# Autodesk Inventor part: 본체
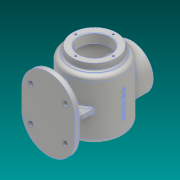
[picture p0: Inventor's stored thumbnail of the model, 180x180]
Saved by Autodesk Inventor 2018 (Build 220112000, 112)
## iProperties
Created: 2023-01
Part Number: 본체
Material: 알루미늄 6061
Document SubType Name: Modeling
Designer: 강의실01
Density: 2.7 g/cm^3
Appearance: 알루미늄 - 평지
Mass: 1034.39 g
Surface Area: 1157.53 cm^2
Volume: 383.109 cm^3
Author: 강의실01
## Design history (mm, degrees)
sketch "스케치1"
  geometry: L1 (46, -63)-(-46, -63); L2 (-46, -63)-(-46, 63); L3 (-46, 63)-(46, 63); L4 (46, 63)-(46, -63); L5 (46, -63)-(-46, 63); L6 (-46, -63)-(46, 63); 1 further point
  constraints: 12 end point, 2 midpoint, 2 parallel, 1 horizontal, 1 perpendicular
  dimensions: "d0" = 92 distance of L2.end L3.end; "d1" = 126 distance of L1.end L2.end
extrude "돌출1" new body sketch "스케치1" distance "d2" = 10; taper "d3" = 0 deg
sketch "스케치2"
  geometry: L1 (0, 63)-(0, -63) reference; L2 (107, 63)-(107, 46); L3 (107, 46)-(125, 46); L4 (118, 51)-(130, 51); L5 (130, 51)-(130, -48.087); L6 (125, 46)-(125, -44.83); L7 (118, 63)-(118, 51); L8 (80, 59)-(80, -59); L9 (107, 63)-(118, 63); A1 r 120 centre (80, 61) between (80, -59) and (130, -48.087); A2 r 115 centre (80, 61) between (80, -54) and (125, -44.83); 3 further points
  constraints: 16 end point, 4 point on circle, 3 perpendicular, 3 vertical, 2 centre point, 2 midpoint, 1 horizontal, 1 horizontal alignment, 1 point on line
  dimensions: "d20" = 5 distance between parallel lines of L6 L5; "d21" = 54 diameter of L2 L8; "d22" = 76 diameter of L7 L8; "d23" = 90 diameter of L6 L8; "d26" = 100 diameter of L5 L8 (derived); "d120" = 59 vertical distance of L8.end point (0, 0); "d122" = 160 diameter of L1 L8; "d124" = 17 distance between parallel lines of L3 L9; "d125" = 5 distance between parallel lines of L3 L4; "d126" = 120 radius of A1; "d127" = 5 radial gap between concentric circles of A1 A2; "d128" = 122 distance from line of L8.end L9 (derived); "d129" = 80 distance from line of A1.centre L1; "d133" = 51 distance from line of point (80, 0) L4
revolve "회전1" sketch "스케치2" stored, may be unused: angle "d39" = 90 deg
node "작업 평면1"
sketch "스케치3"
  geometry: L1 (-50, 51)-(50, 51) reference; C1 r 38 at (0, 0); 1 further point
  constraints: 1 centre point
  dimensions: "d41" = 76 diameter of C1; "d42" = 51 distance from line of L1 C1.centre; "d43" = 71.42129 distance of L1.end C1.centre
extrude "돌출2" join sketch "스케치3" stored distance "d44" = 10; taper "d45" = 0 deg
hole "구멍1" diameter "d48" = 54; stored, may be unused: countersink angle "d52" = 90 deg, drill point angle "d54" = 0 deg; dims "d46" = 10, "d47" = 10, "d49" = 6, "d50" = 4, "d51" = 2, "d53" = 30
sketch "스케치4" dims "d55" = 65
  geometry: L1 (50, -51)-(-50, -51) reference; C1 r 27 at (0, 0) reference; 3 further points
  constraints: 1 coincident, 1 vertical alignment, 2 other
  dimensions: "d56" = 83.5 distance from line of L1 point (0, 32.5)
hole "구멍2" sketch "스케치4" at (0, 32.5) diameter "d57" = 3.242; stored, may be unused: countersink angle "d61" = 90 deg, drill point angle "d63" = 118 deg; dims "d58" = 8, "d59" = 4, "d60" = 2, "d62" = 10
sketch "스케치5" dims "d67" = 65
  geometry: L1 (46, -80)-(-46, -80) reference; 3 further points
  constraints: 1 horizontal alignment, 2 other
  dimensions: "d68" = 80 distance from line of L1 point (-32.5, 0); "d69" = 80 distance from line of point (0, 0) L1; "d70" = 92.28218 distance of L1.start point (0, 0)
hole "구멍3" sketch "스케치5" at (-32.5, 0) diameter "d71" = 3.242; stored, may be unused: countersink angle "d75" = 90 deg, drill point angle "d77" = 118 deg; dims "d72" = 8, "d73" = 4, "d74" = 2, "d76" = 10
sketch "스케치6"
  geometry: L1 (46, 10)-(-46, 10) reference; L2 (-35, 10)-(-35, 44.293); L3 (35, 44.293)-(35, 10); A1 r 50 centre (0, 80) between (-35, 44.293) and (35, 44.293) reference; 1 further point
  constraints: 4 end point, 2 point on circle, 2 point on line, 1 perpendicular, 1 vertical
  dimensions: "d81" = 35 horizontal distance of L3.end point (0, 0); "d82" = 70 distance of L2.start L3.end
extrude "돌출3" join sketch "스케치6" stored distance "d83" = 10; taper "d84" = 0 deg
sketch "스케치7"
  geometry: L1 (10, -63)-(10, 63) reference; L2 (10, -40)-(30, -34.641); L3 (30, 51)-(30, -48.087) reference; 1 further point
  constraints: 2 end point, 2 point on line
  dimensions: "d85" = 105 deg angle of L2 L1; "d86" = 40 vertical distance of point (0, 0) L2.start
feature "리브1" sketch "스케치7" dims "d87" = 1, "d88" = 10, "d89" = 0, "d90" = 0, "d91" = 1, "d92" = 1
fillet "모깎기1" dims "d93" = 46, "d108" = 8
sketch "스케치8"
  geometry: 3 further points
  dimensions: "d97" = 30 horizontal distance of point (0, 0) point (-30, -30); "d98" = 60 distance of point (30, -30) point (-30, -30); "d99" = 30 horizontal distance of point (-30, -30) point (0, 0); "d100" = 30 horizontal distance of point (30, -30) point (0, 0)
hole "구멍4" sketch "스케치8" at (-30, -30), (30, -30) diameter "d101" = 9; stored, may be unused: countersink angle "d105" = 90 deg, drill point angle "d107" = 0 deg; dims "d102" = 8, "d103" = 4, "d104" = 2, "d106" = 10
node "작업 평면2"
sketch "스케치9"
  geometry: L1 (42, 63)-(118, 63) reference; 2 further points
  constraints: 1 other
  dimensions: "d110" = 80 distance of point (0, 0) point (80, 0); "d111" = 63 distance from line of L1 point (80, 0)
feature "엠보싱1" sketch "스케치9" dims "d0" = 92, "d1" = 126, "d112" = 0.5, "d113" = 0
chamfer "모따기1" distance "d114" = 1; stored, may be unused: second distance "d115" = 2, angle "d116" = 45 deg
fillet "모깎기2" dims "d117" = 3
fillet "모깎기3" dims "d118" = 3
chamfer "모따기2" distance "d135" = 1; stored, may be unused: second distance "d136" = 2, angle "d137" = 45 deg
node "솔리드1"
pattern_circular "원형 패턴1" dims angle "d65" = 360 deg
pattern_circular "원형 패턴2" dims angle "d79" = 360 deg
mirror "미러1"
mirror "미러2"
other parameters: "d13" = 76, "d40" = 144
